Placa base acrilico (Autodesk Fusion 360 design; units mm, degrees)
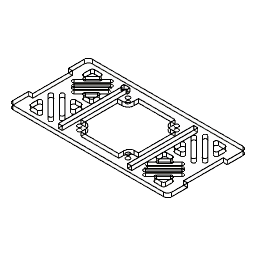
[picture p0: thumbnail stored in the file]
part number: 2026-07-18-00-35-20-214
parameter "d44" = 45
sketch "Boceto1" plane through (0, 0, 0) normal (0, 0, 1) x axis (1, 0, 0)
  line L1 (120, 0) -> (0, 0)
  line L2 (120, 15) -> (120, 0)
  line L3 (117, 15) -> (120, 15)
  line L4 (117, 45) -> (117, 15)
  line L5 (120, 45) -> (117, 45)
  line L6 (120, 60) -> (120, 45)
  line L7 (0, 60) -> (120, 60)
  line L8 (0, 45) -> (0, 60)
  line L9 (3, 45) -> (0, 45)
  line L10 (3, 15) -> (3, 45)
  line L11 (0, 15) -> (3, 15)
  line L12 (0, 0) -> (0, 15)
  line L13 (60, 60) -> (0, 60)
  line L14 (60, 51.75) -> (60, 60)
  line L15 (81.75, 51.75) -> (60, 51.75)
  line L16 (81.75, 8.25) -> (81.75, 51.75)
  line L17 (38.25, 8.25) -> (81.75, 8.25)
  line L18 (38.25, 51.75) -> (38.25, 8.25)
  line L19 (60, 51.75) -> (38.25, 51.75)
  line L20 (84.75, 55) -> (84.75, 51.75)
  line L21 (87.75, 55) -> (84.75, 55)
  line L22 (87.75, 5) -> (87.75, 55)
  line L23 (84.75, 5) -> (87.75, 5)
  line L24 (84.75, 5) -> (84.75, 55)
  line L25 (35.25, 55) -> (35.25, 51.75)
  line L26 (32.25, 55) -> (35.25, 55)
  line L27 (32.25, 5) -> (32.25, 55)
  line L28 (35.25, 5) -> (32.25, 5)
  line L29 (35.25, 5) -> (35.25, 55)
  line L30 (78.35, 51.75) -> (81.75, 51.75)
  line L31 (81.75, 48.35) -> (81.75, 51.75)
  line L32 (81.75, 43.8) -> (78.35, 43.8)
  line L33 (73.8, 51.75) -> (73.8, 48.35)
  line L34 (81.75, 11.65) -> (81.75, 8.25)
  line L35 (78.35, 8.25) -> (81.75, 8.25)
  line L36 (81.75, 16.2) -> (78.35, 16.2)
  line L37 (41.65, 8.25) -> (38.25, 8.25)
  line L38 (46.2, 8.25) -> (46.2, 11.65)
  line L39 (38.25, 16.2) -> (41.65, 16.2)
  line L40 (41.65, 51.75) -> (38.25, 51.75)
  line L41 (46.2, 51.75) -> (46.2, 48.35)
  line L42 (38.25, 43.8) -> (41.65, 43.8)
  curve K1 (78.35, 16.2) -> (78.35, 7.1)
  curve K2 (74.8, 11.65) -> (81.9, 11.65)
  line L43 (74.8, 8.25) -> (74.8, 11.65)
  circle C1 centre (78.35, 48.35) radius 1.55
  circle C2 centre (78.35, 48.35) radius 4.55
  circle C3 centre (78.35, 11.65) radius 1.55
  circle C4 centre (41.65, 11.65) radius 1.55
  circle C5 centre (41.65, 11.65) radius 4.55
  circle C6 centre (41.65, 48.35) radius 1.55
  circle C7 centre (41.65, 48.35) radius 4.55
  closed curve K3 centre (78.35, 11.65)
  point P1 (0, 0)
  point P2 (0, 0)
  point P14 (60, 60)
  point P33 (73.8, 48.35)
  point P36 (81.75, 43.8)
  point P37 (73.8, 51.75)
  point P42 (81.75, 16.2)
  point P45 (46.2, 11.65)
  point P47 (46.2, 8.25)
  point P48 (41.65, 16.2)
  point P49 (38.25, 16.2)
  point P52 (46.2, 48.35)
  point P54 (46.2, 51.75)
  point P55 (41.65, 43.8)
  point P56 (38.25, 43.8)
  point P59 (78.35, 7.1)
  point P60 (78.35, 16.2)
  point P61 (81.9, 11.65)
  point P62 (74.8, 11.65)
  point P41 (78.35, 16.2)
  point P57 (74.8, 11.65)
  point P63 (74.8, 8.25)
  point P3 (120, 0)
  point P4 (120, 15)
  point P5 (117, 15)
  point P6 (117, 45)
  point P7 (120, 45)
  point P8 (120, 60)
  point P15 (60, 51.75)
  point P16 (81.75, 51.75)
  point P17 (81.75, 8.25)
  point P18 (38.25, 8.25)
  point P19 (38.25, 51.75)
  point P20 (84.75, 51.75)
  point P21 (84.75, 55)
  point P22 (87.75, 55)
  point P23 (87.75, 5)
  point P24 (84.75, 5)
  point P25 (35.25, 51.75)
  point P26 (35.25, 55)
  point P27 (32.25, 55)
  point P28 (32.25, 5)
  point P29 (35.25, 5)
  point P30 (78.35, 51.75)
  point P32 (81.75, 48.35)
  point P38 (81.75, 11.65)
  point P40 (78.35, 8.25)
  point P43 (41.65, 8.25)
  point P50 (41.65, 51.75)
  coincident P1 P2
  horizontal L1
  perpendicular L1 L2
  perpendicular L2 L3
  perpendicular L3 L4
  perpendicular L4 L5
  perpendicular L5 L6
  perpendicular L6 L7
  perpendicular L7 L8
  perpendicular L8 L9
  perpendicular L7 L10
  perpendicular L10 L11
  perpendicular L1 L12
  midpoint L7 P14
  perpendicular L13 L14
  perpendicular L14 L15
  perpendicular L15 L16
  perpendicular L16 L17
  perpendicular L17 L18
  perpendicular L16 L21
  perpendicular L21 L22
  perpendicular L22 L23
  perpendicular L25 L26
  perpendicular L26 L27
  perpendicular L27 L28
  perpendicular L16 L30
  perpendicular L30 L31
  coincident P33 C2
  coincident L16 P36
  perpendicular L16 L32
  coincident L15 P37
  tangent C2 L33
  perpendicular L15 L33
  perpendicular L17 L34
  perpendicular L16 L35
  coincident L16 P42
  perpendicular L18 L37
  coincident P45 C5
  coincident L17 P47
  tangent C5 L38
  coincident C5 P48
  coincident L18 P49
  tangent C5 L39
  perpendicular L18 L40
  concentric C6 C7
  coincident P52 C7
  coincident L19 P54
  tangent C7 L41
  coincident C7 P55
  coincident L18 P56
  tangent C7 L42
  coincident K3 P59
  coincident K3 P60
  coincident K3 P61
  coincident K3 P62
  concentric C3 K3
  coincident P41 P60
  perpendicular L36 K1
  coincident P57 P62
  coincident L17 P63
  tangent K3 L43
  perpendicular L17 L43
  dimension "d1" distance P2 P3 = 120
  dimension "d2" distance P3 P4 = 15
  dimension "d3" distance P4 P5 = 3
  dimension "d4" distance P5 P6 = 30
  dimension "d5" distance P7 P8 = 15
  dimension "d6" distance P14 P15 = 8.25
  dimension "d7" distance P15 P16 = 21.75
  dimension "d8" distance P16 P17 = 43.5
  dimension "d9" distance P17 P18 = 43.5
  dimension "d10" distance P18 P19 = 43.5
  dimension "d11" distance P16 P20 = 3
  dimension "d12" distance P21 P22 = 3
  dimension "d13" distance P23 P24 = 3
  dimension "d14" distance P19 P25 = 3
  dimension "d15" distance P26 P27 = 3
  dimension "d16" distance P28 P29 = 3
  dimension "d17" distance P16 P30 = 3.4
  dimension "d19" distance P16 P32 = 3.4
  dimension "d20" distance P17 P38 = 3.4
  dimension "d23" distance P17 P40 = 3.4
  dimension "d25" distance P18 P43 = 3.4
  dimension "d29" distance P19 P50 = 3.4
sketch "Boceto2" plane through (0, 0, 0) normal (0, 0, 1) x axis (1, 0, 0)
sketch "Boceto3" plane through (0, 0, 0) normal (0, 0, 1) x axis (1, 0, 0)
extrude "Extruir1" new body sketch "Boceto1" profile of L1 L2 L3 L4 L5 L6 L7 L8 L9 L10 L11 L12 L13 L14 L15 L16 L17 L18 L19 L20 L21 L22 L23 L24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 along normal blind 3
sketch "Boceto4" plane through (0, 0, 3) normal (0, 0, 1) x axis (-1, 0, 0)
  line L1 (-46.2, -51.75) -> (-46.2, -48.35)
  line L2 (-73.8, -51.75) -> (-46.2, -51.75)
  line L3 (-73.8, -48.35) -> (-73.8, -51.75)
  line L4 (-81.75, -43.8) -> (-78.35, -43.8)
  line L5 (-81.75, -16.2) -> (-81.75, -43.8)
  line L6 (-78.35, -16.2) -> (-81.75, -16.2)
  line L7 (-74.8, -8.25) -> (-74.8, -11.65)
  line L8 (-46.2, -8.25) -> (-74.8, -8.25)
  line L9 (-46.2, -11.65) -> (-46.2, -8.25)
  line L10 (-38.25, -16.2) -> (-41.65, -16.2)
  line L11 (-38.25, -43.8) -> (-38.25, -16.2)
  line L12 (-41.65, -43.8) -> (-38.25, -43.8)
  line L13 (-87.75, -55) -> (-84.75, -55)
  line L14 (-87.75, -5) -> (-87.75, -55)
  line L15 (-84.75, -5) -> (-87.75, -5)
  line L16 (-84.75, -55) -> (-84.75, -5)
  line L17 (-32.25, -55) -> (-32.25, -5)
  line L18 (-35.25, -55) -> (-32.25, -55)
  line L19 (-35.25, -5) -> (-35.25, -55)
  line L20 (-32.25, -5) -> (-35.25, -5)
  line L21 (0, -60) -> (-120, -60)
  line L22 (0, -45) -> (0, -60)
  line L23 (-3, -45) -> (0, -45)
  line L24 (-3, -15) -> (-3, -45)
  line L25 (0, -15) -> (-3, -15)
  line L26 (0, 0) -> (0, -15)
  line L27 (-120, 0) -> (0, 0)
  line L28 (-120, -15) -> (-120, 0)
  line L29 (-117, -15) -> (-120, -15)
  line L30 (-117, -45) -> (-117, -15)
  line L31 (-120, -45) -> (-117, -45)
  line L32 (-120, -60) -> (-120, -45)
  line L33 (-111, -60) -> (-120, -60)
  line L34 (-111, 0) -> (-111, -60)
  line L35 (-87.75, -60) -> (-87.75, -55)
  line L36 (-90.75, -60) -> (-87.75, -60)
  line L37 (-90.75, 0) -> (-90.75, -60)
  line L38 (-111, -30) -> (-111, -60)
  line L39 (-90.75, -30) -> (-111, -30)
  line L40 (-111, -33) -> (-111, -30)
  line L41 (-90.75, -33) -> (-111, -33)
  line L42 (-111, -27) -> (-111, -30)
  line L43 (-111, -27) -> (-90.75, -27)
  line L44 (-111, -54) -> (-111, -60)
  line L45 (-90.75, -54) -> (-111, -54)
  line L46 (-111, -6) -> (-111, 0)
  line L47 (-90.75, -6) -> (-111, -6)
  line L48 (-90.75, -53.25) -> (-111, -33)
  line L49 (-101.3838, -44.7375) -> (-100.3231, -43.6769)
  line L50 (-99.2625, -42.6162) -> (-101.3838, -44.7375)
  line L51 (-108.8787, -33) -> (-99.2625, -42.6162)
  line L52 (-90.75, -51.1287) -> (-108.8787, -33)
  line L53 (-111, -35.1213) -> (-111, -33)
  line L54 (-92.1213, -54) -> (-111, -35.1213)
  line L55 (-105.6264, -48.9802) -> (-103.5051, -46.8589)
  line L56 (-111, -39.364) -> (-111, -35.1213)
  line L57 (-96.364, -54) -> (-111, -39.364)
  line L58 (-111, -43.6066) -> (-111, -39.364)
  line L59 (-100.6066, -54) -> (-111, -43.6066)
  line L60 (-104.636, -33) -> (-97.1411, -40.4949)
  line L61 (-90.75, -46.886) -> (-97.1411, -40.4949)
  line L62 (-95.0198, -38.3736) -> (-97.1411, -40.4949)
  line L63 (-100.3934, -33) -> (-95.0198, -38.3736)
  line L64 (-90.75, -42.6434) -> (-95.0198, -38.3736)
  line L65 (-90.75, -6) -> (-111, -6)
  line L66 (-90.75, -27) -> (-111, -27)
  line L67 (-100.6066, -6) -> (-111, -16.3934)
  line L68 (-90.75, -17.3566) -> (-95.0198, -21.6264)
  line L69 (-92.1213, -6) -> (-111, -24.8787)
  line L70 (-90.75, -8.8713) -> (-108.8787, -27)
  line L71 (-95.0198, -21.6264) -> (-97.1411, -19.5051)
  line L72 (-104.636, -27) -> (-97.1411, -19.5051)
  line L73 (-101.3838, -15.2625) -> (-100.3231, -16.3231)
  line L74 (-90.75, -13.114) -> (-97.1411, -19.5051)
  line L75 (-99.2625, -17.3838) -> (-101.3838, -15.2625)
  line L76 (-100.3934, -27) -> (-95.0198, -21.6264)
  line L77 (-105.6264, -11.0198) -> (-103.5051, -13.1411)
  line L78 (-96.364, -6) -> (-111, -20.636)
  line L79 (-90.75, -6.75) -> (-111, -27)
  line L80 (-108.8787, -27) -> (-99.2625, -17.3838)
  line L81 (-32.25, -60) -> (-32.25, -55)
  line L82 (-29.25, -60) -> (-32.25, -60)
  line L83 (-29.25, 0) -> (-29.25, -60)
  line L84 (-9, -60) -> (0, -60)
  line L85 (-9, 0) -> (-9, -60)
  line L86 (-9, -30) -> (-29.25, -30)
  line L87 (-9, -33) -> (-9, -30)
  line L88 (-9, -33) -> (-9, -30)
  line L89 (-29.25, -33) -> (-9, -33)
  line L90 (-29.25, -27) -> (-29.25, -30)
  line L91 (-9, -27) -> (-29.25, -27)
  line L92 (-9, -54) -> (-9, -33)
  line L93 (-29.25, -54) -> (-9, -54)
  line L94 (-29.25, -6) -> (-29.25, -27)
  line L95 (-9, -6) -> (-29.25, -6)
  line L96 (-9, -27) -> (-9, -33)
  line L97 (-29.25, -6) -> (-9, -6)
  line L98 (-11.1213, -27) -> (-20.7375, -17.3838)
  line L99 (-15.364, -27) -> (-22.8589, -19.5051)
  line L100 (-29.25, -6.75) -> (-9, -27)
  line L101 (-29.25, -8.8713) -> (-11.1213, -27)
  line L102 (-23.636, -6) -> (-9, -20.636)
  line L103 (-14.3736, -11.0198) -> (-16.4949, -13.1411)
  line L104 (-24.9802, -38.3736) -> (-22.8589, -40.4949)
  line L105 (-29.25, -33) -> (-9, -33)
  line L106 (-11.1213, -33) -> (-20.7375, -42.6162)
  line L107 (-9, -27) -> (-29.25, -27)
  line L108 (-29.25, -27) -> (-9, -27)
  line L109 (-29.25, -17.3566) -> (-24.9802, -21.6264)
  line L110 (-29.25, -54) -> (-9, -54)
  line L111 (-20.7375, -17.3838) -> (-18.6162, -15.2625)
  line L112 (-15.364, -33) -> (-22.8589, -40.4949)
  line L113 (-20.7375, -42.6162) -> (-18.6162, -44.7375)
  line L114 (-18.6162, -44.7375) -> (-19.6769, -43.6769)
  line L115 (-29.25, -42.6434) -> (-24.9802, -38.3736)
  line L116 (-29.25, -53.25) -> (-9, -33)
  line L117 (-29.25, -6) -> (-9, -6)
  line L118 (-24.9802, -21.6264) -> (-22.8589, -19.5051)
  line L119 (-18.6162, -15.2625) -> (-19.6769, -16.3231)
  line L120 (-27.8787, -6) -> (-9, -24.8787)
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  point P30 (-120, -60)
  point P42 (-120, -60)
  point P43 (-111, -60)
  point P44 (-111, 0)
  point P23 (-87.75, -55)
  point P45 (-87.75, -55)
  point P46 (-87.75, -60)
  point P48 (-90.75, 0)
  point P49 (-111, -30)
  point P50 (-90.75, -30)
  point P51 (-111, -33)
  point P52 (-90.75, -33)
  point P53 (-111, -27)
  point P54 (-90.75, -27)
  point P55 (-111, -54)
  point P56 (-90.75, -54)
  point P57 (-111, -6)
  point P58 (-90.75, -6)
  point P59 (-90.75, -53.25)
  point P60 (-100.3231, -43.6769)
  point P63 (-108.8787, -33)
  point P64 (-90.75, -51.1287)
  point P65 (-111, -35.1213)
  point P66 (-92.1213, -54)
  point P69 (-111, -39.364)
  point P70 (-96.364, -54)
  point P71 (-111, -43.6066)
  point P72 (-100.6066, -54)
  point P74 (-104.636, -33)
  point P75 (-90.75, -46.886)
  point P77 (-100.3934, -33)
  point P78 (-90.75, -42.6434)
  point P27 (-32.25, -55)
  point P125 (-32.25, -55)
  point P126 (-32.25, -60)
  point P128 (-29.25, 0)
  point P31 (0, -60)
  point P129 (0, -60)
  point P130 (-9, -60)
  point P131 (-9, 0)
  point P132 (-29.25, -30)
  point P133 (-9, -30)
  point P134 (-9, -33)
  point P135 (-29.25, -33)
  point P136 (-29.25, -27)
  point P137 (-9, -27)
  point P139 (-29.25, -54)
  point P141 (-9, -6)
  point P142 (-9, -33)
  point P205 (-9, -33)
  point P143 (-9, -27)
  point P145 (-9, -27)
  point P47 (-90.75, -60)
  point P61 (-101.3838, -44.7375)
  point P62 (-99.2625, -42.6162)
  point P67 (-103.5051, -46.8589)
  point P68 (-105.6264, -48.9802)
  point P73 (-97.1411, -40.4949)
  point P76 (-95.0198, -38.3736)
  point P127 (-29.25, -60)
  point P138 (-9, -54)
  point P140 (-29.25, -6)
  coincident P30 P42
  coincident L21 P43
  coincident L27 P44
  perpendicular L27 L34
  coincident P23 P45
  coincident L21 P46
  perpendicular L21 L35
  perpendicular L35 L36
  coincident L27 P48
  perpendicular L27 L37
  midpoint L34 P49
  midpoint L37 P50
  coincident L38 P51
  coincident L37 P52
  perpendicular L37 L41
  coincident L34 P53
  coincident L37 P54
  perpendicular L34 L43
  coincident L38 P55
  coincident L37 P56
  perpendicular L37 L45
  coincident L34 P57
  coincident L37 P58
  perpendicular L37 L47
  equal L44 L46
  coincident L37 P59
  coincident L48 P60
  perpendicular L48 L49
  perpendicular L48 L50
  coincident L41 P63
  perpendicular L50 L51
  coincident L37 P64
  parallel L48 L52
  coincident L34 P65
  coincident L45 P66
  parallel L48 L54
  perpendicular L48 L55
  coincident L34 P69
  coincident L45 P70
  coincident L38 P71
  coincident L45 P72
  parallel L57 L59
  coincident L41 P74
  coincident L37 P75
  perpendicular L60 L62
  coincident L41 P77
  perpendicular L62 L63
  coincident L37 P78
  perpendicular L62 L64
  coincident P27 P125
  coincident L21 P126
  perpendicular L21 L81
  perpendicular L17 L82
  coincident L27 P128
  perpendicular L27 L83
  coincident P31 P129
  coincident L21 P130
  coincident L27 P131
  perpendicular L27 L85
  midpoint L83 P132
  midpoint L85 P133
  coincident L85 P134
  coincident L83 P135
  perpendicular L83 L89
  coincident L83 P136
  coincident L85 P137
  perpendicular L85 L91
  perpendicular L89 L92
  coincident L83 P139
  perpendicular L83 L93
  perpendicular L91 L94
  coincident L85 P141
  perpendicular L85 L95
  symmetric P142 L96 P205
  symmetric P143 L96 P145
  dimension "d35" distance P46 P47 = 3
  dimension "d36" distance L21 L41 = 27
  dimension "d37" distance L32 L40 = 9
  dimension "d38" distance L41 L45 = 21
  dimension "d40" distance P50 L43 = 3
  dimension "d42" distance P60 P61 = 1.5
  dimension "d43" distance P61 P62 = 3
  dimension "d45" distance P61 P67 = 3
  dimension "d46" distance P67 P68 = 3
  dimension "d47" distance P62 P73 = 3
  dimension "d48" distance P73 P76 = 3
  dimension "d49" diameter = 3
  dimension "d50" diameter = 3
  dimension "d51" diameter = 3
  dimension "d52" diameter = 3
  dimension "d53" diameter = 3
  dimension "d54" diameter = 3
  dimension "d55" diameter = 3
  dimension "d56" diameter = 3
  dimension "d57" diameter = 3
  dimension "d58" diameter = 3
  dimension "d76" distance P126 P127 = 3
  dimension "d77" distance P134 P138 = 21
  dimension "d78" distance P136 P140 = 21
extrude "Extruir2" cut sketch "Boceto4" against normal blind 6
fillet "Empalme" radius 3
sketch "Boceto5" plane through (0, 0, 3) normal (0, 0, 1) x axis (-1, 0, 0)
  line L1 (-3, -60) -> (-117, -60)
  line L2 (0, -45) -> (0, -57)
  line L3 (-3, -45) -> (0, -45)
  line L4 (-3, -15) -> (-3, -45)
  line L5 (0, -15) -> (-3, -15)
  line L6 (0, -3) -> (0, -15)
  line L7 (-117, 0) -> (-3, 0)
  line L8 (-120, -15) -> (-120, -3)
  line L9 (-117, -15) -> (-120, -15)
  line L10 (-117, -45) -> (-117, -15)
  line L11 (-120, -45) -> (-117, -45)
  line L12 (-120, -57) -> (-120, -45)
  line L13 (-32.25, -55) -> (-32.25, -5)
  line L14 (-35.25, -55) -> (-32.25, -55)
  line L15 (-35.25, -5) -> (-35.25, -55)
  line L16 (-32.25, -5) -> (-35.25, -5)
  line L17 (-87.75, -55) -> (-84.75, -55)
  line L18 (-87.75, -5) -> (-87.75, -55)
  line L19 (-84.75, -5) -> (-87.75, -5)
  line L20 (-84.75, -55) -> (-84.75, -5)
  line L21 (-46.2, -51.75) -> (-46.2, -48.35)
  line L22 (-73.8, -51.75) -> (-46.2, -51.75)
  line L23 (-73.8, -48.35) -> (-73.8, -51.75)
  line L24 (-81.75, -43.8) -> (-78.35, -43.8)
  line L25 (-81.75, -16.2) -> (-81.75, -43.8)
  line L26 (-78.35, -16.2) -> (-81.75, -16.2)
  line L27 (-74.8, -8.25) -> (-74.8, -11.65)
  line L28 (-46.2, -8.25) -> (-74.8, -8.25)
  line L29 (-46.2, -11.65) -> (-46.2, -8.25)
  line L30 (-38.25, -16.2) -> (-41.65, -16.2)
  line L31 (-38.25, -43.8) -> (-38.25, -16.2)
  line L32 (-41.65, -43.8) -> (-38.25, -43.8)
  line L33 (-108.4393, -13.8327) -> (-103.1673, -8.5607)
  line L34 (-111, -7.5) -> (-111, -12.7721)
  line L35 (-104.2279, -6) -> (-109.5, -6)
  line L36 (-110.5607, -39.8033) -> (-96.8033, -53.5607)
  line L37 (-94.682, -51.4393) -> (-108.4393, -37.682)
  line L38 (-16.8327, -8.5607) -> (-11.5607, -13.8327)
  line L39 (-10.5, -6) -> (-15.7721, -6)
  line L40 (-9, -12.7721) -> (-9, -7.5)
  line L41 (-9.4393, -20.1967) -> (-23.1967, -6.4393)
  line L42 (-25.318, -8.5607) -> (-11.5607, -22.318)
  line L43 (-11.5607, -37.682) -> (-25.318, -51.4393)
  line L44 (-23.1967, -53.5607) -> (-9.4393, -39.8033)
  line L45 (-15.8033, -33.4393) -> (-28.8107, -46.4467)
  line L46 (-26.6893, -48.568) -> (-13.682, -35.5607)
  line L47 (-91.1893, -46.4467) -> (-104.1967, -33.4393)
  line L48 (-106.318, -35.5607) -> (-93.3107, -48.568)
  line L49 (-90.75, -25.5) -> (-90.75, -20.9779)
  line L50 (-96.7721, -27) -> (-92.25, -27)
  line L51 (-93.3107, -19.9173) -> (-97.8327, -24.4393)
  line L52 (-108.4393, -22.318) -> (-94.682, -8.5607)
  line L53 (-96.8033, -6.4393) -> (-110.5607, -20.1967)
  line L54 (-109.5, -54) -> (-104.2279, -54)
  line L55 (-111, -47.2279) -> (-111, -52.5)
  line L56 (-103.1673, -51.4393) -> (-108.4393, -46.1673)
  line L57 (-28.8107, -13.5533) -> (-15.8033, -26.5607)
  line L58 (-13.682, -24.4393) -> (-26.6893, -11.432)
  line L59 (-9, -52.5) -> (-9, -47.2279)
  line L60 (-15.7721, -54) -> (-10.5, -54)
  line L61 (-11.5607, -46.1673) -> (-16.8327, -51.4393)
  line L62 (-29.25, -34.5) -> (-29.25, -39.0221)
  line L63 (-23.2279, -33) -> (-27.75, -33)
  line L64 (-26.6893, -40.0827) -> (-22.1673, -35.5607)
  line L65 (-27.75, -27) -> (-23.2279, -27)
  line L66 (-29.25, -20.9779) -> (-29.25, -25.5)
  line L67 (-22.1673, -24.4393) -> (-26.6893, -19.9173)
  line L68 (-90.75, -39.0221) -> (-90.75, -34.5)
  line L69 (-97.8327, -35.5607) -> (-93.3107, -40.0827)
  line L70 (-92.25, -33) -> (-96.7721, -33)
  line L71 (-104.1967, -26.5607) -> (-91.1893, -13.5533)
  line L72 (-93.3107, -11.432) -> (-106.318, -24.4393)
  line L73 (-36, -55.5) -> (-33.75, -55.5)
  line L74 (-31.5, -55.5) -> (-33.75, -55.5)
  line L75 (-31.5, -53.25) -> (-31.5, -55.5)
  line L76 (-36, -53.25) -> (-36, -55.5)
  line L77 (-32.25, -53.25) -> (-31.5, -53.25)
  line L78 (-36, -53.25) -> (-35.25, -53.25)
  arc A1 centre (-117, -57) radius 3 clockwise from (-117, -60) to (-120, -57)
  arc A2 centre (-3, -57) radius 3 clockwise from (0, -57) to (-3, -60)
  arc A3 centre (-3, -3) radius 3 clockwise from (-3, 0) to (0, -3)
  arc A4 centre (-117, -3) radius 3 clockwise from (-120, -3) to (-117, 0)
  circle C1 centre (-41.65, -48.35) radius 1.55
  circle C2 centre (-41.65, -11.65) radius 1.55
  circle C3 centre (-78.35, -11.65) radius 1.55
  circle C4 centre (-78.35, -48.35) radius 1.55
  arc A5 centre (-78.35, -48.35) radius 4.55 clockwise from (-78.35, -43.8) to (-73.8, -48.35)
  closed curve K1 centre (-78.35, -11.65)
  arc A6 centre (-41.65, -11.65) radius 4.55 clockwise from (-41.65, -16.2) to (-46.2, -11.65)
  arc A7 centre (-41.65, -48.35) radius 4.55 clockwise from (-46.2, -48.35) to (-41.65, -43.8)
  arc A8 centre (-109.5, -12.7721) radius 1.5 clockwise from (-108.4393, -13.8327) to (-111, -12.7721)
  arc A9 centre (-109.5, -7.5) radius 1.5 clockwise from (-111, -7.5) to (-109.5, -6)
  arc A10 centre (-104.2279, -7.5) radius 1.5 clockwise from (-104.2279, -6) to (-103.1673, -8.5607)
  arc A11 centre (-109.5, -38.7426) radius 1.5 clockwise from (-110.5607, -39.8033) to (-108.4393, -37.682)
  arc A12 centre (-95.7426, -52.5) radius 1.5 clockwise from (-94.682, -51.4393) to (-96.8033, -53.5607)
  arc A13 centre (-10.5, -12.7721) radius 1.5 clockwise from (-9, -12.7721) to (-11.5607, -13.8327)
  arc A14 centre (-15.7721, -7.5) radius 1.5 clockwise from (-16.8327, -8.5607) to (-15.7721, -6)
  arc A15 centre (-10.5, -7.5) radius 1.5 clockwise from (-10.5, -6) to (-9, -7.5)
  arc A16 centre (-10.5, -21.2574) radius 1.5 clockwise from (-9.4393, -20.1967) to (-11.5607, -22.318)
  arc A17 centre (-24.2574, -7.5) radius 1.5 clockwise from (-25.318, -8.5607) to (-23.1967, -6.4393)
  arc A18 centre (-10.5, -38.7426) radius 1.5 clockwise from (-11.5607, -37.682) to (-9.4393, -39.8033)
  arc A19 centre (-24.2574, -52.5) radius 1.5 clockwise from (-23.1967, -53.5607) to (-25.318, -51.4393)
  arc A20 centre (-14.7426, -34.5) radius 1.5 clockwise from (-15.8033, -33.4393) to (-13.682, -35.5607)
  arc A21 centre (-27.75, -47.5074) radius 1.5 clockwise from (-26.6893, -48.568) to (-28.8107, -46.4467)
  arc A22 centre (-105.2574, -34.5) radius 1.5 clockwise from (-106.318, -35.5607) to (-104.1967, -33.4393)
  arc A23 centre (-92.25, -47.5074) radius 1.5 clockwise from (-91.1893, -46.4467) to (-93.3107, -48.568)
  arc A24 centre (-92.25, -20.9779) radius 1.5 clockwise from (-93.3107, -19.9173) to (-90.75, -20.9779)
  arc A25 centre (-92.25, -25.5) radius 1.5 clockwise from (-90.75, -25.5) to (-92.25, -27)
  arc A26 centre (-96.7721, -25.5) radius 1.5 clockwise from (-96.7721, -27) to (-97.8327, -24.4393)
  arc A27 centre (-109.5, -21.2574) radius 1.5 clockwise from (-108.4393, -22.318) to (-110.5607, -20.1967)
  arc A28 centre (-95.7426, -7.5) radius 1.5 clockwise from (-96.8033, -6.4393) to (-94.682, -8.5607)
  arc A29 centre (-104.2279, -52.5) radius 1.5 clockwise from (-103.1673, -51.4393) to (-104.2279, -54)
  arc A30 centre (-109.5, -52.5) radius 1.5 clockwise from (-109.5, -54) to (-111, -52.5)
  arc A31 centre (-109.5, -47.2279) radius 1.5 clockwise from (-111, -47.2279) to (-108.4393, -46.1673)
  arc A32 centre (-14.7426, -25.5) radius 1.5 clockwise from (-13.682, -24.4393) to (-15.8033, -26.5607)
  arc A33 centre (-27.75, -12.4926) radius 1.5 clockwise from (-28.8107, -13.5533) to (-26.6893, -11.432)
  arc A34 centre (-10.5, -52.5) radius 1.5 clockwise from (-9, -52.5) to (-10.5, -54)
  arc A35 centre (-15.7721, -52.5) radius 1.5 clockwise from (-15.7721, -54) to (-16.8327, -51.4393)
  arc A36 centre (-10.5, -47.2279) radius 1.5 clockwise from (-11.5607, -46.1673) to (-9, -47.2279)
  arc A37 centre (-27.75, -34.5) radius 1.5 clockwise from (-29.25, -34.5) to (-27.75, -33)
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  point P175 (-32.25, -53.25)
  point P176 (-35.25, -53.25)
  point P172 (-31.5, -55.5)
  point P173 (-31.5, -53.25)
  perpendicular L74 L75
  perpendicular L73 L76
  coincident L13 P175
  perpendicular L13 L77
  coincident L15 P176
  perpendicular L76 L78
  dimension "d107" distance P172 P173 = 2.25
extrude "Extruir3" cut sketch "Boceto5" profile of L13 L14 L15 L73 L74 L75 L76 L77 L78 against normal blind 3.5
